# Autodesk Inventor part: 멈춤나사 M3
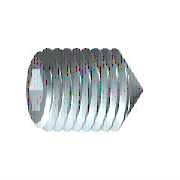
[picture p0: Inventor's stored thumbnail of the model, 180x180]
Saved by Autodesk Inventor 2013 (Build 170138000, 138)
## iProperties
IsCustomPart: 1
Created: 2012-02
Part Number: 멈춤나사 M3
Material: 강철, 연강
Description: 6각 소켓 머리 없는 멈춤 나사
Document SubType Name: Modeling
Standard: KS B 1028
Designer: test
Standards Organization: KS
Language: ko-KR
Size Designation: 원추점 M3x8
Categories: <MemberInstance><Categories><Category DisplayName="조임쇠" InternalName="e4da775c-781d-43d5-af7c-5136215cf5a6" Mnemonic="FSTN"><Category DisplayName="볼트" InternalN
Density: 1 g/cm^3
Author: test
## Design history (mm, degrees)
sketch "스케치1"
  geometry: L1 (0, 0)-(5.5, 0); L2 (8, 0.866)-(8, 1.5); L3 (8, 1.5)-(0, 1.5); L4 (8, 0.866)-(6, 0.866); L5 (6, 0.866)-(5.5, 0); L6 (0, -0.3)-(0, 1.8) reference; L7 (0, 1.5)-(0, 0)
  constraints: 13 end point, 3 parallel, 1 collinear, 1 perpendicular, 1 point on line
  dimensions: "d0" = 2 distance of L2.start L4.end (= INTI); "d1" = 60 deg angle of L5 L1; "d2" = 3 diameter of L3 L1 (= NND); "d3" = 1.73205 diameter of L4 L1 (= 1.1547 x SW); "d5" = 8 distance from line of L2 L3.end (= NLG)
revolve "본체" sketch "스케치1" stored, may be unused: angle "d6" = 90 deg
sketch "스케치2"
  geometry: L1 (-0.433, 0.75)-(0.433, 0.75); L2 (0.433, 0.75)-(0.866, 0); L3 (0.866, 0)-(0.433, -0.75); L4 (0.433, -0.75)-(-0.433, -0.75); L5 (-0.433, -0.75)-(-0.866, 0); L6 (-0.866, 0)-(-0.433, 0.75); 3 further points
  constraints: 12 end point, 1 coincident, 1 horizontal, 13 other
extrude "슬롯" join sketch "스케치2" taper "d7" = 0 deg; stored distance "d21" = 10
workaxis "Work Axis1"
workplane "Work Plane1"
body "Solid1"
feature "스레드" dims "d12" = 8 (= NLG), "d13" = 0
chamfer "모따기1" distance "d8" = 1.35 (computed from NND, SPD, FAWI); stored, may be unused: angle "d9" = 45 deg (= FAWI), second distance "d34" = 1.35 (computed from NND, SPD, FAWI)
chamfer "모따기2" distance "d10" = 0.30673 (= -0.5 x GD1 + 0.5 x NND); stored, may be unused: angle "d11" = 45 deg (= FAWI), second distance "d35" = 0.30673 (= -0.5 x GD1 + 0.5 x NND)
other parameters: "NND" = 3 [user parameter; used in 5 equation terms], "NLG" = 8 [user parameter; used in 2 equation terms], "INTI" = 2 [user parameter; used in 1 equation term], "FAWI" = 45 deg [user parameter; used in 4 equation terms], "SW" = 1.5 [user parameter; used in 2 equation terms], "GD1" = 2.38655 (= THREADDIA - 1.2269 x PTC) [user parameter; used in 2 equation terms], "d4" = 0, "FAWI1" = 45 deg [user parameter], "SPD" = 0.3 [user parameter; used in 2 equation terms], "d36" = 0, "d37" = 0, "GUL" = 0.30673 (= 0.61345 x PTC) [user parameter], "TOA" = 30 deg [user parameter], "THREADDIA" = 3 [user parameter; used in 1 equation term], "PTC" = 0.5 [user parameter; used in 4 equation terms], "GAL" = 0.30673 (= 0.61345 x PTC) [user parameter], "E0" = 1.7325 (= 1.155 x SW) [user parameter]
